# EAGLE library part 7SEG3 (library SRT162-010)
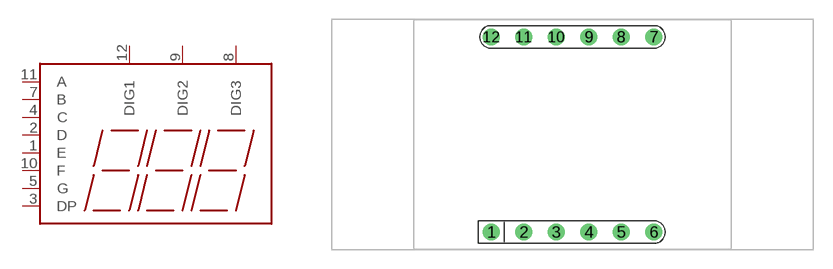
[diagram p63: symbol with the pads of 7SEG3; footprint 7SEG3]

Designator prefix M

## 7SEG3  [7SEG3]
1  E  pas
2  D  pas
3  DP  pas
4  C  pas
5  G  pas
7  B  pas
8  DIG3  pas
9  DIG2  pas
10  F  pas
11  A  pas
12  DIG1  pas

## Footprint 7SEG3 (pad centres in mm)
drill 0.8 round: 1 -6.35,-7.62; 2 -3.81,-7.62; 3 -1.27,-7.62; 4 1.27,-7.62; 5 3.81,-7.62; 6 6.35,-7.62; 7 6.35,7.62; 8 3.81,7.62; 9 1.27,7.62; 10 -1.27,7.62; 11 -3.81,7.62; 12 -6.35,7.62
